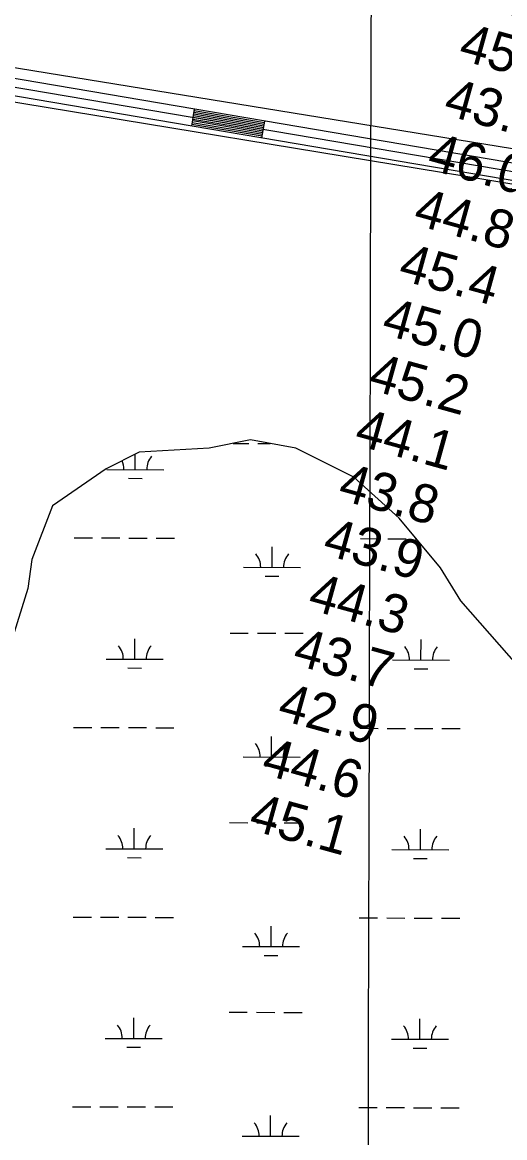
# Model space of a CAD drawing. Extents: x 3161615 to 3199515, y 867541 to 892976.
# Drawn here: x 3186129 to 3186975, y 874724 to 876681 of the extents above; entities that cross this region are included whole.
import ezdxf

# ---------------------------------------------------------------- set-up
doc = ezdxf.new("R2010")
doc.units = 0
for name, color, linetype in [('V-GRID-MAJR', 7, 'Continuous'), ('V-RIVR-RANG', 7, 'Continuous'), ('V-ROAD-CNTR', 7, 'Continuous'), ('V-SITE-VEGE', 7, 'Continuous'), ('V-WETL-SWMP', 7, 'Continuous')]:
    doc.layers.add(name, color=color, linetype=linetype)

msp = doc.modelspace()

# ---------------------------------------------------------------- linework, layer by layer
at = {"layer": 'V-GRID-MAJR'}
msp.add_spline([(3186730.9, 872949.8), (3186746.7, 879009.3), (3186762.6, 885072), (3186778.5, 891134.7), (3186778.5, 891137.7)], degree=3, dxfattribs=at)
at = {"layer": 'V-ROAD-CNTR'}
for p, q in [((3186426, 876498.5), (3186431, 876528.1)), ((3186549.2, 876477.6), (3186554.2, 876507.2))]:
    msp.add_line(p, q, dxfattribs=at)
for points in [[(3187217.2, 876379.5), (3186063.7, 876575.2), (3185238.8, 876705.3), (3184353.1, 876836.2), (3183434.5, 876974.9), (3183096.5, 877027.7), (3182832.3, 877067.9), (3182620.8, 877102.1), (3182566.6, 877107.2), (3182524.7, 877106.8), (3182470.3, 877107.4), (3181710.6, 877110.1), (3181684.7, 877112.3), (3181660.7, 877115)], [(3187219.7, 876394.3), (3186066.1, 876590), (3185383, 876697.7)], [(3187214.7, 876364.7), (3186061.2, 876560.4), (3185394.8, 876665.5)], [(3186550.7, 876486.5), (3186427.5, 876507.4)], [(3186551.2, 876489.4), (3186428, 876510.3)], [(3186551.7, 876492.4), (3186428.5, 876513.3)], [(3186552.2, 876495.3), (3186429, 876516.2)], [(3186552.7, 876498.3), (3186429.5, 876519.2)], [(3186553.2, 876501.3), (3186430, 876522.2)], [(3186553.7, 876504.2), (3186430.5, 876525.1)], [(3186549.7, 876480.6), (3186426.5, 876501.5)], [(3186550.2, 876483.5), (3186427, 876504.4)]]:
    msp.add_lwpolyline(points, dxfattribs=at)
at = {"layer": 'V-SITE-VEGE'}
for p, q in [((3186910.4, 876409.2), (3185500.4, 876641.8)), ((3187692.1, 876280.5), (3186910.4, 876409.2))]:
    msp.add_line(p, q, dxfattribs=at)
msp.add_lwpolyline([(3188389.6, 876701.2), (3188389.6, 876636.9), (3188384.7, 876557.7), (3188369.9, 876483.4), (3188374.8, 876419.1), (3188384.7, 876364.6), (3188364.9, 876295.3), (3188325.3, 876245.8), (3188275.9, 876231), (3188231.3, 876231), (3187657.4, 876349.8), (3185525.1, 876696.3)], dxfattribs=at)
at = {"layer": 'V-WETL-SWMP'}
for p, q in [((3186529.2, 875947.9), (3186456.9, 875933.4)), ((3186498.7, 875941.8), (3186526.2, 875941.7)), ((3186608.8, 875933.4), (3186529.2, 875947.9)), ((3186542.2, 875941.7), (3186563.8, 875941.6)), ((3186333.9, 875926.2), (3186276, 875897.2)), ((3186327, 875895.9), (3186327.1, 875922.8)), ((3186456.9, 875933.4), (3186333.9, 875926.2)), ((3186710.1, 875882.8), (3186608.8, 875933.4)), ((3186276, 875897.2), (3186181.9, 875832.1)), ((3186277, 875896), (3186377, 875895.7)), ((3186315, 875880.5), (3186339, 875880.4)), ((3186789.7, 875810.4), (3186710.1, 875882.8)), ((3186181.9, 875832.1), (3186145.8, 875737.9)), ((3186862.1, 875723.5), (3186789.7, 875810.4)), ((3186219.9, 875776.1), (3186251.9, 875776)), ((3186267.9, 875775.9), (3186299.9, 875775.9)), ((3186315.9, 875775.8), (3186347.9, 875775.7)), ((3186363.9, 875775.7), (3186395.9, 875775.6)), ((3186721.8, 875774.7), (3186753.8, 875774.6)), ((3186769.8, 875774.6), (3186801.8, 875774.5)), ((3186817.8, 875774.4), (3186819.6, 875774.4)), ((3186567, 875724.4), (3186567.1, 875760.4)), ((3186145.8, 875737.9), (3186138.5, 875687.3)), ((3186517, 875724.5), (3186617, 875724.2)), ((3186555, 875709), (3186579, 875708.9)), ((3186898.2, 875665.5), (3186862.1, 875723.5)), ((3186138.5, 875687.3), (3186109.6, 875593.1)), ((3186999.5, 875549.7), (3186898.2, 875665.5)), ((3186493.3, 875609.1), (3186525.3, 875609.1)), ((3186541.3, 875609), (3186573.3, 875608.9)), ((3186589.3, 875608.9), (3186621.3, 875608.8)), ((3186326.1, 875563.2), (3186326.2, 875599.2)), ((3186828, 875561.8), (3186828.1, 875597.8)), ((3186276.1, 875563.3), (3186376.1, 875563)), ((3186314.1, 875547.8), (3186338.1, 875547.7)), ((3186778, 875561.9), (3186878, 875561.7)), ((3186816, 875546.4), (3186840, 875546.3)), ((3186218.9, 875443.4), (3186250.9, 875443.3)), ((3186266.9, 875443.3), (3186298.9, 875443.2)), ((3186314.9, 875443.1), (3186346.9, 875443.1)), ((3186362.9, 875443), (3186394.9, 875442.9)), ((3186720.8, 875442), (3186752.8, 875441.9)), ((3186768.8, 875441.9), (3186800.8, 875441.8)), ((3186816.8, 875441.8), (3186848.8, 875441.7)), ((3186864.8, 875441.6), (3186896.8, 875441.5)), ((3186566.1, 875391.7), (3186566.2, 875427.7)), ((3186516.1, 875391.8), (3186616.1, 875391.6)), ((3186554.1, 875376.3), (3186578.1, 875376.2)), ((3186492.4, 875276.5), (3186524.4, 875276.4)), ((3186540.4, 875276.3), (3186572.4, 875276.3)), ((3186588.4, 875276.2), (3186620.4, 875276.1)), ((3186325.2, 875230.5), (3186325.3, 875266.5)), ((3186827.1, 875229.1), (3186827.2, 875265.1)), ((3186275.2, 875230.6), (3186375.2, 875230.4)), ((3186313.2, 875215.1), (3186337.2, 875215)), ((3186777.1, 875229.3), (3186877.1, 875229)), ((3186815.1, 875213.7), (3186839.1, 875213.7)), ((3186218, 875110.7), (3186250, 875110.6)), ((3186266, 875110.6), (3186298, 875110.5)), ((3186314, 875110.5), (3186346, 875110.4)), ((3186362, 875110.3), (3186394, 875110.2)), ((3186719.9, 875109.3), (3186751.9, 875109.3)), ((3186767.9, 875109.2), (3186799.9, 875109.1)), ((3186815.9, 875109.1), (3186847.9, 875109)), ((3186863.9, 875108.9), (3186895.9, 875108.9)), ((3186565.2, 875059), (3186565.3, 875095)), ((3186515.2, 875059.2), (3186615.2, 875058.9)), ((3186553.1, 875043.6), (3186577.1, 875043.6)), ((3186491.5, 874943.8), (3186523.5, 874943.7)), ((3186539.5, 874943.7), (3186571.5, 874943.6)), ((3186587.5, 874943.5), (3186619.5, 874943.4)), ((3186324.3, 874897.8), (3186324.4, 874933.8)), ((3186826.2, 874896.4), (3186826.3, 874932.4)), ((3186274.3, 874898), (3186374.3, 874897.7)), ((3186312.2, 874882.4), (3186336.2, 874882.4)), ((3186776.2, 874896.6), (3186876.2, 874896.3)), ((3186814.1, 874881), (3186838.1, 874881)), ((3186217.1, 874778.1), (3186249.1, 874778)), ((3186265.1, 874777.9), (3186297.1, 874777.8)), ((3186313.1, 874777.8), (3186345.1, 874777.7)), ((3186361.1, 874777.7), (3186393.1, 874777.6)), ((3186719, 874776.7), (3186751, 874776.6)), ((3186767, 874776.5), (3186799, 874776.5)), ((3186815, 874776.4), (3186847, 874776.3)), ((3186863, 874776.3), (3186895, 874776.2)), ((3186564.3, 874726.4), (3186564.4, 874762.4)), ((3186514.3, 874726.5), (3186614.3, 874726.2))]:
    msp.add_line(p, q, dxfattribs=at)
for centre, start, end in [((3186271.8, 875896.5), 359.0699, 24.6306), ((3186382.3, 875896.2), 139.0699, 180.6135), ((3186511.8, 875725), 359.0699, 40.6135), ((3186622.3, 875724.7), 139.0699, 180.6135), ((3186270.9, 875563.8), 359.0699, 40.6135), ((3186381.4, 875563.5), 139.0699, 180.6135), ((3186772.8, 875562.4), 359.0699, 40.6135), ((3186883.3, 875562.1), 139.0699, 180.6135), ((3186510.9, 875392.3), 359.0699, 40.6135), ((3186621.4, 875392), 139.0699, 180.6135), ((3186270, 875231.1), 359.0699, 40.6135), ((3186380.4, 875230.8), 139.0699, 180.6135), ((3186771.9, 875229.7), 359.0699, 40.6135), ((3186882.3, 875229.4), 139.0699, 180.6135), ((3186510, 875059.7), 359.0699, 40.6135), ((3186620.4, 875059.4), 139.0699, 180.6135), ((3186269, 874898.5), 359.0699, 40.6135), ((3186379.5, 874898.2), 139.0699, 180.6135), ((3186770.9, 874897.1), 359.0699, 40.6135), ((3186881.4, 874896.8), 139.0699, 180.6135), ((3186509, 874727), 359.0699, 40.6135), ((3186619.5, 874726.7), 139.0699, 180.6135)]:
    msp.add_arc(centre, 35.2, start, end, dxfattribs=at)

# ---------------------------------------------------------------- texts
at = {"layer": 'V-RIVR-RANG'}
for s, p in [('46.8', (3186918.1, 876712.3)), ('45.9', (3186891.4, 876615.9)), ('43.8', (3186865.2, 876519.4)), ('46.0', (3186836, 876423.8)), ('44.8', (3186812.3, 876326.6)), ('45.4', (3186785.8, 876230.1)), ('45.0', (3186756.6, 876134.5)), ('45.2', (3186732.9, 876037.3)), ('44.1', (3186708.8, 875940.2)), ('43.8', (3186680, 875844.4)), ('43.9', (3186653.3, 875748)), ('44.3', (3186627.1, 875651.5)), ('43.7', (3186600.6, 875555.1)), ('42.9', (3186573.9, 875458.7)), ('44.6', (3186545.9, 875362.7)), ('45.1', (3186523.6, 875265.1))]:
    msp.add_text(s, height=67, rotation=344.5183, dxfattribs=at).set_placement(p)

doc.saveas('drawing.dxf')
